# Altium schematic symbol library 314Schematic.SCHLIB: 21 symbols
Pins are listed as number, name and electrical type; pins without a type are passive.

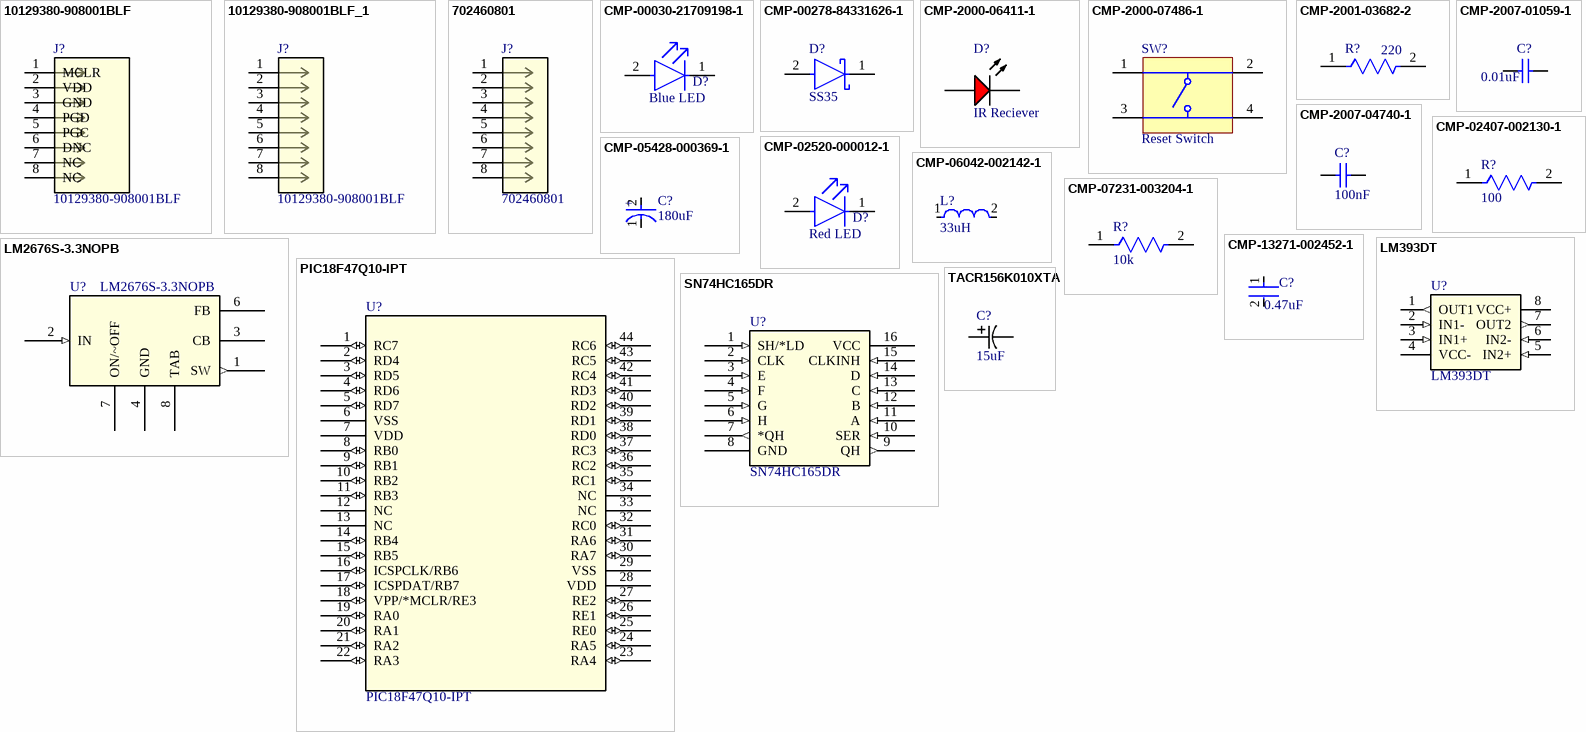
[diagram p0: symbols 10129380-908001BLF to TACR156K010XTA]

## 10129380-908001BLF
designator J?
No Description Available; Mfr_Name: Amphenol ICC
footprint CONN_10129380-x08001xLF_AMP
pins: 1 MCLR, 2 VDD, 3 GND, 4 PGD, 5 PGC, 6 DNC, 7 NC, 8 NC

## 10129380-908001BLF_1
designator J?, comment 10129380-908001BLF
No Description Available; Mfr_Name: Amphenol ICC
footprint CONN_10129380-x08001xLF_AMP
pins: 1, 2, 3, 4, 5, 6, 7, 8

## 702460801
designator J?
No Description Available; Mfr_Name: Molex Connector Corporation
footprint CONN_7024608xx_MOL
pins: 1, 2, 3, 4, 5, 6, 7, 8

## CMP-00030-21709198-1
designator D?, comment Blue LED
VLMB1310-GS08 LED Uni-Color Blue 468nm 2-Pin Chip 0603(1608Metric) T/R; NexarPartId: 21709198; Forward Voltage: 3.8V; Forward Current: 20mA; Wavelength: 475nm; Viewing Angle: 130°; Luminous Intensity: 180mcd; Lens Style: Clear, Rectangular; Number of LEDs: 1; Power Rating: 75mW; Dominant Wavelength: 470nm
footprint FP-6_541-5093_01-4-MFG (LED Uni-Color Blue 468nm 2-Pin Chip 0603(1608Metric) T/R)
pins: 1 C, 2 A

## CMP-00278-84331626-1
designator D?, comment SS35
SS35 Rectifier Diode, Schottky, 1 Phase, 1 Element, 3A, 50V V(RRM), Silicon, DO-214AB; Manufacturer Lifecycle Status: ACTIVE, NOT REC; NexarPartId: 84331626; Max Forward Surge Current (Ifsm): 100A; Forward Voltage: 750mV; Max Reverse Leakage Current: 500µA; Element Configuration: Single; Polarity: Standard
footprint FP-403AG-MFG (Rectifier Diode, Schottky, 1 Phase, 1 Element, 3A, 50V V(RRM), Silicon, DO-214AB)
pins: 1 C, 2 A

## CMP-2000-06411-1
designator D?, comment IR Reciever
T-1 3/4 (5 mm) Diffused LED Lamp, 1.9 V, -40 to 100 degC, 2-Pin THD, RoHS, Bulk; Manufacturer: Avago; Forward Current: 25mA; Forward Voltage: 2.4V; Peak Wavelength: 635nm; Shape Type: Circular; High Brightness: No; Main Category: StandardLED; Test Current (It): 10mA; Dominant Wave Length: 626nm; Number of  Elements: 1; Reverse Voltage: 5V; Chip Material: GaP; Product Height (mm): 9.19mm; Lens Type: ColoredDiffused; Viewing Angle: 60deg; Type: Uni-Color; Emitting Color: Red; Luminous Intensity: 5.4mcd; Power Dissipation: 85W; DELETED: Compliant; Product Depth (mm): 6.1mm
footprint AVAG-HLMP-3301-2 (THD, 2-Leads, Body Dia 5.85mm)
pins: 1 K, 2 A

## CMP-2000-07486-1
designator SW?, comment Reset Switch
Micro Miniature Push Button Switch FSM JSM, 50 mA, -35 to 85 degC, 4-Pin SMD, RoHS, Tape and Reel; Manufacturer: TE Connectivity; Mechanical Life: 100000Cycles; Current Rating: 50mA; Actuator Material: Polyamide; Max Voltage Rating (DC): 12V; Capacitance: 0f; Illumination Type: Illuminated; Voltage Rating (DC): 24V; Case\/Package: SMD/SMT; Operating Force: 160gf; Contact Resistance: 100mOhm; Actuator Length: 0.055inch; Switch Travel: 0.25mm; Throw Configuration: SPST
footprint TECO-FSM4JSMATR_V (SMD, 4-Leads, Body 6x6mm, Pitch 4.5mm)
pins: 1, 2, 3, 4

## CMP-2001-03682-2
designator R?, comment 220
RES Thick Film, 220Ω, 1%, 0.125W, 100ppm/°C, 0805; Max Power Dissipation: 125mW; Voltage Rating: 150V; Resistance: 220R
footprint FP-CRCW0805-e3-MFG
footprint FP-CRCW0805-e3-IPC_C
footprint FP-CRCW0805-e3-IPC_A
footprint FP-CRCW0805-e3-IPC_B
pins: 1, 2

## CMP-2007-01059-1
designator C?, comment 0.01uF
Manufacturer: Kemet; Part Number: C0805W103KCRACTU
footprint CAPC2013X145X50ML20T25 (Chip Capacitor, 2-Leads, Body 2.00x1.25mm, IPC Low Density)
footprint CAPC2013X145X50LL20T25 (Chip Capacitor, 2-Leads, Body 2.00x1.25mm, IPC High Density)
footprint CAPC2013X145X50NL20T25 (Chip Capacitor, 2-Leads, Body 2.00x1.25mm, IPC Medium Density)
pins: 1, 2
1 alternate drawing of the same symbol

## CMP-2007-04740-1
designator C?, comment 100nF
Part Number: 08051C104M4Z2A; Manufacturer: AVX Interconnect / Elco
footprint CAPC2013X140X50LL20T25 (Chip Capacitor, 2-Leads, Body 2.00x1.25mm, IPC High Density)
footprint CAPC2013X140X50ML20T25 (Chip Capacitor, 2-Leads, Body 2.00x1.25mm, IPC Low Density)
footprint CAPC2013X140X50NL20T25 (Chip Capacitor, 2-Leads, Body 2.00x1.25mm, IPC Medium Density)
pins: 1, 2
1 alternate drawing of the same symbol

## CMP-02407-002130-1
designator R?, comment 100
RES Thick Film, 100Ω, 5%, 0.5W, 200ppm/°C, 0805; Voltage Rating: 150V; Resistance: 100R; Power Rating: 330mW; Max Power Dissipation: 333mW
footprint FP-CRCW0805-HPe3-IPC_C
footprint FP-CRCW0805-HPe3-IPC_A
footprint FP-CRCW0805-HPe3-MFG
footprint FP-CRCW0805-HPe3-IPC_B
pins: 1, 2

## CMP-02520-000012-1
designator D?, comment Red LED
LED RED 0603 SMD; Manufacturer: Vishay; Manufacturer Part Number: VLMS1300-GS08; Forward Voltage: 2V; Reverse Voltage: 5V; Power Dissipation: 75mW; Description: Red 631nm LED Indication - Discrete 2V 0603 (1608 Metric); Forward Current: 20mA; Luminous Intensity: 54mcd; Led Orientation: Top View; Peak Emmision Wavelength: 639nm; Viewing Angle: 130°; Wavelength: 631nm
footprint FP-6_541-5092_01-4-MFG
pins: 1 C, 2 A

## CMP-05428-000369-1
designator C?, comment 180uF
Molded Aluminum Polymer Capacitor 180uF 20% 2V life 2000Hours SMD 2917; ESR (Equivalent Series Resistance): 9mR; Life (Hours): 1000Hour; Ripple Current: 3A; Dielectric Material: Aluminium; Dissipation Factor: 0.06%; Leakage Current: 36uA
footprint FP-SP-Cap-X-MFG
pins: 1 C, 2 A

## CMP-06042-002142-1
designator L?, comment 33uH
Wire Wound Ferrite Inductor for Power Lines 33μH ±10% 1.43Ω 200mA 1210; Test Frequency: 1MHz; Shielding: Unshielded; DC Resistance (DCR): 1.1R; Self Resonant Frequency: 17MHz
footprint FP-LQH32CH_53-MFG
pins: 1, 2

## CMP-07231-003204-1
designator R?, comment 10k
Thick Film Chip Resistors 0805 10kΩ 0.125W 1% 100ppm/°C; Max Power Dissipation: 125mW; Voltage Rating: 150V; Voltage Rating (DC): 100V; Resistance: 10kR
footprint FP-CR0805-IPC_A
footprint FP-CR0805-MFG
footprint FP-CR0805-IPC_B
footprint FP-CR0805-IPC_C
pins: 1, 2

## CMP-13271-002452-1
designator C?, comment 0.47uF
CL21 Series 0805 470nF 50V ±10% Tolerance X7R Multilayer Ceramic Chip Capacitor
footprint FP-CL21-IPC_A
footprint FP-CL21-IPC_B
footprint FP-CL21-IPC_C
pins: 1, 2

## LM393DT
designator U?
No Description Available; Mfr_Name: STMicroelectronics
footprint SO8_STM
pins: 1 OUT1 (out), 2 IN1- (in), 3 IN1+ (in), 4 VCC- (power), 5 IN2+ (in), 6 IN2- (in), 7 OUT2 (out), 8 VCC+ (power)

## LM2676S-3.3NOPB
designator U?
No Description Available; Mfr_Name: Texas Instruments
footprint TS7B
pins: 1 SW (out), 2 IN (in), 3 CB, 4 GND, 6 FB, 7 ON/~OFF, 8 TAB

## PIC18F47Q10-IPT
designator U?
No Description Available; Mfr_Name: Microchip
footprint TQFP44_PT_MCH
pins: 1 RC7 (io), 2 RD4 (io), 3 RD5 (io), 4 RD6 (io), 5 RD7 (io), 6 VSS (power), 7 VDD (power), 8 RB0 (io), 9 RB1 (io), 10 RB2 (io), 11 RB3 (io), 12 NC, 13 NC, 14 RB4 (io), 15 RB5 (io), 16 ICSPCLK/RB6 (io), 17 ICSPDAT/RB7 (io), 18 VPP/*MCLR/RE3 (io), 19 RA0 (io), 20 RA1 (io), 21 RA2 (io), 22 RA3 (io), 23 RA4 (io), 24 RA5 (io), 25 RE0 (io), 26 RE1 (io), 27 RE2 (io), 28 VDD (power), 29 VSS (power), 30 RA7 (io), 31 RA6 (io), 32 RC0 (io), 33 NC, 34 NC, 35 RC1 (io), 36 RC2 (io), 37 RC3 (io), 38 RD0 (io), 39 RD1 (io), 40 RD2 (io), 41 RD3 (io), 42 RC4 (io), 43 RC5 (io), 44 RC6 (io)

## SN74HC165DR
designator U?
No Description Available; Mfr_Name: Texas Instruments
footprint D16
pins: 1 SH/*LD (in), 2 CLK (in), 3 E (in), 4 F (in), 5 G (in), 6 H (in), 7 *QH (out), 8 GND (power), 9 QH (out), 10 SER (in), 11 A (in), 12 B (in), 13 C (in), 14 D (in), 15 CLKINH (in), 16 VCC (power)

## TACR156K010XTA
designator C?, comment 15uF
No Description Available; Mfr_Name: KYOCERA AVX
footprint TACR_AVX
pins: 1, 2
